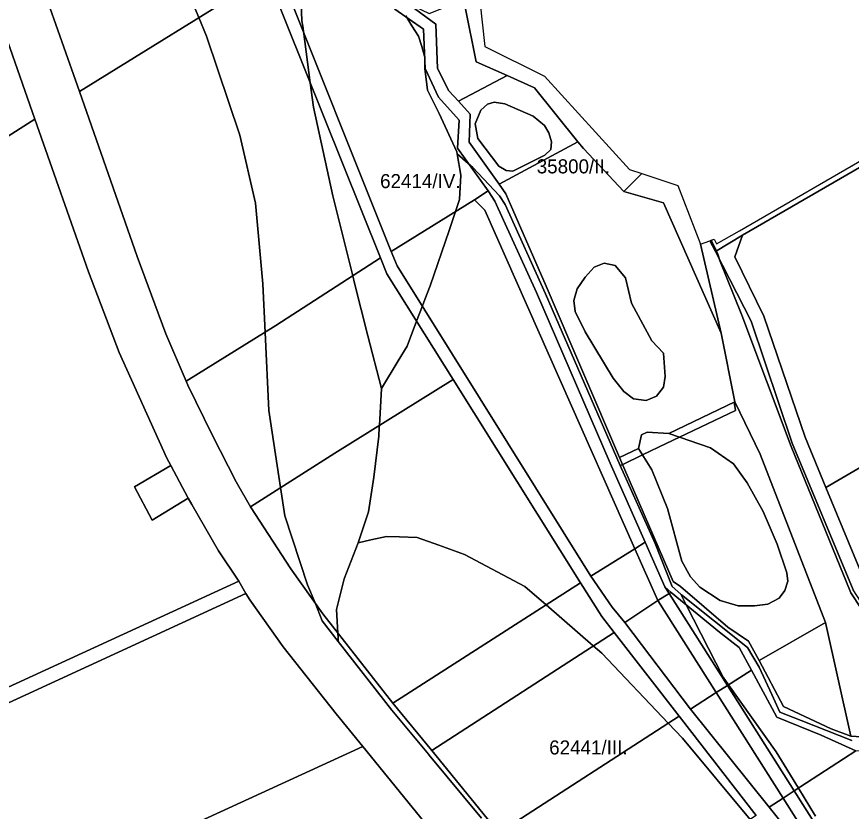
# Model space of a CAD drawing. Extents: x -522079 to -518833, y -1142400 to -1139961.
# Drawn here: x -520985.3 to -520688.5, y -1140520.9 to -1140238.4 of the extents above; entities that cross this region are included whole.
import ezdxf

# ---------------------------------------------------------------- set-up
doc = ezdxf.new("R2010")
doc.units = 0
for name, color, linetype in [('95560013', 7, 'Continuous'), ('95610013', 7, 'Continuous'), ('95620013', 7, 'Continuous'), ('95630013', 7, 'Continuous'), ('95640013', 7, 'Continuous'), ('95660013', 7, 'Continuous')]:
    doc.layers.add(name, color=color, linetype=linetype)

msp = doc.modelspace()

# ---------------------------------------------------------------- linework, layer by layer
at = {"layer": '95560013'}
for points in [[(-520697.54, -1140405.82), (-520704.93, -1140387.92), (-520719.64, -1140344.89), (-520729.96, -1140323.84), (-520727.12, -1140316.09), (-520610.57, -1140248.68), (-520489.41, -1140176.97), (-520443.64, -1140149.48), (-520437.53, -1140151.12), (-520407.86, -1140236.34), (-520563.45, -1140327.62)], [(-520896.25, -1140223.69), (-520963.03, -1140264.99), (-520975.5, -1140229.32), (-520909.48, -1140190.7)], [(-520863.77, -1140204.01), (-520859.87, -1140225.61), (-520850.88, -1140235.71), (-520840.6, -1140242.88), (-520840.04, -1140256.81), (-520835.3, -1140267.04), (-520827.93, -1140275.18), (-520828.6, -1140285.19), (-520817.67, -1140300.36), (-520822.46, -1140303.46), (-520852.13, -1140321.93), (-520892.27, -1140221.28)], [(-520963.03, -1140264.99), (-520896.25, -1140223.69), (-520855.89, -1140324.19), (-520893.13, -1140348.26), (-520925.04, -1140368.05), (-520932.27, -1140351.12), (-520942.5, -1140323.7)], [(-520407.86, -1140236.34), (-520389.24, -1140289.48), (-520535.21, -1140374.77), (-520673.87, -1140455.8), (-520683.48, -1140439.85), (-520697.54, -1140405.82), (-520563.45, -1140327.62)], [(-521144.75, -1140380.49), (-521166.55, -1140356.84), (-521138.04, -1140336), (-521105.44, -1140313.39), (-521071.25, -1140292.13), (-521029.36, -1140265.01), (-520991.34, -1140239.5), (-520978.89, -1140274.79)], [(-520943.46, -1140405.56), (-520937.19, -1140417.44), (-520924.28, -1140409.64), (-520923.06, -1140411.9), (-520913.58, -1140428.33), (-520906.37, -1140439.12), (-521031.07, -1140496.4), (-521039.03, -1140495.22), (-521144.75, -1140380.49), (-520978.89, -1140274.79), (-520959.74, -1140329.07), (-520948.85, -1140357.77), (-520931.92, -1140395.43), (-520930.52, -1140398.04)], [(-520853.68, -1140329.78), (-520830.07, -1140367.42), (-520872.15, -1140393.54), (-520902.19, -1140412.67), (-520907.24, -1140403.74), (-520915.77, -1140387.04), (-520924.44, -1140369.44), (-520925.04, -1140368.05), (-520893.13, -1140348.26), (-520855.89, -1140324.19)], [(-520781.06, -1140437.3), (-520765.49, -1140427.57), (-520757.32, -1140446.02), (-520769.04, -1140453.82), (-520773.55, -1140448.4)], [(-520851.49, -1140482.48), (-520784.75, -1140439.67), (-520777.25, -1140451.62), (-520772.84, -1140457.31), (-520837.71, -1140499.35)], [(-521174.07, -1140567.72), (-521038.29, -1140505.39), (-520903.84, -1140443.54), (-520902.4, -1140445.74), (-520890.58, -1140462.46), (-520871.65, -1140486.28), (-520862.22, -1140497.87), (-521134.28, -1140622.71), (-521175.11, -1140573.76)], [(-520757.32, -1140446.02), (-520736.54, -1140478.75), (-520745.68, -1140484.57), (-520769.04, -1140453.82)], [(-520837.71, -1140499.35), (-520772.84, -1140457.31), (-520749.72, -1140487.1), (-520813.81, -1140528.62)], [(-520736.54, -1140478.75), (-520712.75, -1140516.21), (-520717.71, -1140519.42), (-520745.68, -1140484.57)], [(-520785.9, -1140562.81), (-520813.81, -1140528.62), (-520749.72, -1140487.1), (-520722.28, -1140522.46), (-520735.82, -1140531.09)], [(-520862.22, -1140497.87), (-520765.71, -1140616.57), (-520897.82, -1140676.39), (-521036.95, -1140739.4), (-521134.28, -1140622.71)], [(-520712.75, -1140516.21), (-520692.27, -1140548.47), (-520693.7, -1140549.35), (-520717.71, -1140519.42)]]:
    msp.add_lwpolyline(points, close=True, dxfattribs=at)
msp.add_lwpolyline([(-520722.28, -1140522.46), (-520749.72, -1140487.1), (-520772.84, -1140457.31), (-520777.25, -1140451.62), (-520784.75, -1140439.67), (-520830.07, -1140367.42), (-520853.68, -1140329.78), (-520855.89, -1140324.19), (-520896.25, -1140223.69), (-520909.48, -1140190.7), (-520905.41, -1140188.32), (-520892.27, -1140221.28), (-520852.13, -1140321.93), (-520849.95, -1140326.96), (-520781.06, -1140437.3), (-520773.55, -1140448.4), (-520769.04, -1140453.82), (-520745.68, -1140484.57), (-520717.71, -1140519.42), (-520693.7, -1140549.35)], dxfattribs=at)
at = {"layer": '95610013'}
for points in [[(-520831.58, -1140264.76), (-520835.7, -1140256.78), (-520836.21, -1140241.05), (-520847.4, -1140232.82), (-520856.59, -1140222.67), (-520843.85, -1140234.81), (-520838.62, -1140237.3), (-520834.17, -1140235.54), (-520832.49, -1140233.14), (-520829.57, -1140196.57), (-520831.74, -1140193.15), (-520834.84, -1140193.48), (-520857.8, -1140202.58), (-520859.91, -1140204.51), (-520858.48, -1140201.26), (-520811.93, -1140174.77), (-520818.11, -1140203.91), (-520825.87, -1140235.03), (-520821.91, -1140254.48), (-520810.93, -1140259.32), (-520828.22, -1140268.46)], [(-520828.22, -1140268.46), (-520810.93, -1140259.32), (-520801.15, -1140263.64), (-520785.74, -1140282.9), (-520813.67, -1140297.99), (-520824.45, -1140283.03), (-520824.03, -1140273.06)], [(-520817.84, -1140269.53), (-520820.3, -1140271.64), (-520822.29, -1140276.46), (-520821.31, -1140281.75), (-520813.83, -1140291.57), (-520811.29, -1140293.11), (-520808.84, -1140293.29), (-520797.46, -1140287.61), (-520795.38, -1140285.61), (-520795.15, -1140282.87), (-520796.05, -1140279.66), (-520797.56, -1140277.1), (-520801.58, -1140273.72), (-520811.67, -1140269.37), (-520815.5, -1140268.8)], [(-520783.73, -1140285.25), (-520769.34, -1140300.61), (-520755.22, -1140304.57), (-520734.8, -1140350.95), (-520729.88, -1140375.38), (-520753.32, -1140386.65), (-520761.05, -1140386.08), (-520763.05, -1140387.08), (-520764.21, -1140391.88), (-520770.87, -1140395.08), (-520797.01, -1140334.21), (-520811.33, -1140301.33), (-520813.67, -1140297.99), (-520785.74, -1140282.9)], [(-520754.64, -1140366.29), (-520755.29, -1140358.03), (-520759.43, -1140353.7), (-520766.65, -1140340.21), (-520768.74, -1140331.28), (-520772.48, -1140326.88), (-520776.36, -1140326.07), (-520779.88, -1140327.47), (-520783.19, -1140331.06), (-520785.95, -1140335.16), (-520787.17, -1140339.26), (-520786.73, -1140343.23), (-520783.16, -1140350.46), (-520773.17, -1140366.91), (-520769.43, -1140371.66), (-520765.93, -1140374.29), (-520761.4, -1140374.89), (-520757.78, -1140373.33), (-520755.28, -1140370.09)], [(-520752.54, -1140443.09), (-520753.24, -1140443.52), (-520754.76, -1140441.12)], [(-520735.34, -1140457.3), (-520728.4, -1140462.65), (-520724, -1140470.78), (-520732.54, -1140476.21), (-520753.24, -1140443.52), (-520752.54, -1140443.09)], [(-520732.54, -1140476.21), (-520724, -1140470.78), (-520714.97, -1140487.48), (-520699.14, -1140493.81), (-520686.89, -1140499.45), (-520708.82, -1140513.67)], [(-520686.89, -1140499.45), (-520675.92, -1140498.77), (-520661.91, -1140491.42), (-520635.69, -1140488.94), (-520617.72, -1140496.63), (-520614.24, -1140500.69), (-520688.32, -1140546.05), (-520708.82, -1140513.67)]]:
    msp.add_lwpolyline(points, close=True, dxfattribs=at)
at = {"layer": '95620013'}
for points in [[(-520849.95, -1140326.96), (-520852.13, -1140321.93), (-520822.46, -1140303.46), (-520818.84, -1140307.19), (-520765.49, -1140427.57), (-520781.06, -1140437.3)], [(-520902.19, -1140412.67), (-520872.15, -1140393.54), (-520830.07, -1140367.42), (-520784.75, -1140439.67), (-520851.49, -1140482.48), (-520876.46, -1140450.75), (-520887.82, -1140434.78)]]:
    msp.add_lwpolyline(points, close=True, dxfattribs=at)
at = {"layer": '95630013'}
for points in [[(-520821.47, -1140225.09), (-520818.83, -1140248.97), (-520797.63, -1140259.52), (-520767.33, -1140292.73), (-520763.01, -1140294.16), (-520769.34, -1140300.61), (-520783.73, -1140285.25), (-520785.74, -1140282.9), (-520801.15, -1140263.64), (-520810.93, -1140259.32), (-520821.91, -1140254.48), (-520825.87, -1140235.03)], [(-520847.4, -1140232.82), (-520836.21, -1140241.05), (-520835.7, -1140256.78), (-520831.58, -1140264.76), (-520828.22, -1140268.46), (-520824.03, -1140273.06), (-520824.45, -1140283.03), (-520813.67, -1140297.99), (-520811.33, -1140301.33), (-520797.01, -1140334.21), (-520770.87, -1140395.08), (-520751.81, -1140439.25), (-520749.19, -1140441.04), (-520732.44, -1140455.44), (-520725.07, -1140460.42), (-520721.21, -1140467.33), (-520712.6, -1140483.62), (-520695.64, -1140491.57), (-520688.63, -1140494.17), (-520677.55, -1140494.96)], [(-520686.89, -1140499.45), (-520699.14, -1140493.81), (-520714.97, -1140487.48), (-520724, -1140470.78), (-520728.4, -1140462.65), (-520735.34, -1140457.3), (-520752.54, -1140443.09), (-520754.76, -1140441.12), (-520761.78, -1140425.25), (-520774.21, -1140397.13), (-520800.48, -1140336.51), (-520815.23, -1140303.96), (-520817.67, -1140300.36), (-520828.6, -1140285.19), (-520827.93, -1140275.18), (-520835.3, -1140267.04), (-520840.04, -1140256.81), (-520840.6, -1140242.88), (-520850.88, -1140235.71)], [(-520677.55, -1140494.96), (-520688.63, -1140494.17), (-520697.67, -1140453.81), (-520720.9, -1140393.9), (-520729.88, -1140375.38), (-520734.8, -1140350.95), (-520755.22, -1140304.57), (-520769.34, -1140300.61), (-520763.01, -1140294.16), (-520750.13, -1140298.42), (-520742.16, -1140319.24), (-520738.8, -1140318.04), (-520736.79, -1140321.94), (-520724.04, -1140346.68), (-520709.46, -1140390.03), (-520687.78, -1140442.24)]]:
    msp.add_lwpolyline(points, dxfattribs=at)
for points in [[(-520795.15, -1140282.87), (-520795.38, -1140285.61), (-520797.46, -1140287.61), (-520808.84, -1140293.29), (-520811.29, -1140293.11), (-520813.83, -1140291.57), (-520821.31, -1140281.75), (-520822.29, -1140276.46), (-520820.3, -1140271.64), (-520817.84, -1140269.53), (-520815.5, -1140268.8), (-520811.67, -1140269.37), (-520801.58, -1140273.72), (-520797.56, -1140277.1), (-520796.05, -1140279.66)], [(-520768.74, -1140331.28), (-520766.65, -1140340.21), (-520759.43, -1140353.7), (-520755.29, -1140358.03), (-520754.64, -1140366.29), (-520755.28, -1140370.09), (-520757.78, -1140373.33), (-520761.4, -1140374.89), (-520765.93, -1140374.29), (-520769.43, -1140371.66), (-520773.17, -1140366.91), (-520783.16, -1140350.46), (-520786.73, -1140343.23), (-520787.17, -1140339.26), (-520785.95, -1140335.16), (-520783.19, -1140331.06), (-520779.88, -1140327.47), (-520776.36, -1140326.07), (-520772.48, -1140326.88)], [(-520729.88, -1140375.38), (-520720.9, -1140393.9), (-520697.67, -1140453.81), (-520721.21, -1140467.33), (-520725.07, -1140460.42), (-520732.44, -1140455.44), (-520749.19, -1140441.04), (-520751.81, -1140439.25), (-520770.87, -1140395.08), (-520764.21, -1140391.88), (-520759.4, -1140399.48), (-520753.83, -1140413.22), (-520748.72, -1140432.03), (-520745.71, -1140437.58), (-520742.3, -1140441.21), (-520735.07, -1140445.99), (-520728.76, -1140447.85), (-520722.88, -1140447.92), (-520718.16, -1140447.28), (-520714.17, -1140445.14), (-520712.14, -1140442.41), (-520711.04, -1140439.09), (-520711.41, -1140436.09), (-520714.9, -1140426), (-520719.87, -1140414.3), (-520725.51, -1140404.14), (-520730.43, -1140397.36), (-520738.54, -1140391.69), (-520753.32, -1140386.65)], [(-520753.32, -1140386.65), (-520738.54, -1140391.69), (-520730.43, -1140397.36), (-520725.51, -1140404.14), (-520719.87, -1140414.3), (-520714.9, -1140426), (-520711.41, -1140436.09), (-520711.04, -1140439.09), (-520712.14, -1140442.41), (-520714.17, -1140445.14), (-520718.16, -1140447.28), (-520722.88, -1140447.92), (-520728.76, -1140447.85), (-520735.07, -1140445.99), (-520742.3, -1140441.21), (-520745.71, -1140437.58), (-520748.72, -1140432.03), (-520753.83, -1140413.22), (-520759.4, -1140399.48), (-520764.21, -1140391.88), (-520763.05, -1140387.08), (-520761.05, -1140386.08)]]:
    msp.add_lwpolyline(points, close=True, dxfattribs=at)
at = {"layer": '95640013'}
for points in [[(-520489.41, -1140176.97), (-520610.57, -1140248.68), (-520727.12, -1140316.09), (-520736.79, -1140321.94), (-520738.8, -1140318.04), (-520737.2, -1140317.47), (-520736.37, -1140319.22), (-520728.21, -1140314.51), (-520611.62, -1140247.2), (-520491.09, -1140175.17)], [(-520989.57, -1140189.1), (-520981.4, -1140212.45), (-520975.5, -1140229.32), (-520963.03, -1140264.99), (-520942.5, -1140323.7), (-520932.27, -1140351.12), (-520925.04, -1140368.05), (-520924.44, -1140369.44), (-520915.77, -1140387.04), (-520907.24, -1140403.74), (-520902.19, -1140412.67), (-520887.82, -1140434.78), (-520876.46, -1140450.75), (-520851.49, -1140482.48), (-520837.71, -1140499.35), (-520813.81, -1140528.62)], [(-520765.71, -1140616.57), (-520862.22, -1140497.87), (-520871.65, -1140486.28), (-520890.58, -1140462.46), (-520902.4, -1140445.74), (-520903.84, -1140443.54), (-520906.37, -1140439.12), (-520913.58, -1140428.33), (-520923.06, -1140411.9), (-520924.28, -1140409.64), (-520930.52, -1140398.04), (-520931.92, -1140395.43), (-520948.85, -1140357.77), (-520959.74, -1140329.07), (-520978.89, -1140274.79), (-520991.34, -1140239.5)], [(-520560.63, -1140549.81), (-520611.7, -1140490.5), (-520625.05, -1140483.49), (-520666, -1140475.86), (-520687.78, -1140442.24), (-520709.46, -1140390.03), (-520724.04, -1140346.68), (-520736.79, -1140321.94), (-520727.12, -1140316.09), (-520729.96, -1140323.84), (-520719.64, -1140344.89), (-520704.93, -1140387.92), (-520697.54, -1140405.82), (-520683.48, -1140439.85), (-520673.87, -1140455.8), (-520666.98, -1140467.24), (-520659.41, -1140472.47), (-520623.97, -1140478.75), (-520608.7, -1140486.32), (-520592.52, -1140504.62), (-520587.65, -1140510.13), (-520562.49, -1140540.48)]]:
    msp.add_lwpolyline(points, dxfattribs=at)
for points in [[(-520822.46, -1140303.46), (-520817.67, -1140300.36), (-520815.23, -1140303.96), (-520800.48, -1140336.51), (-520774.21, -1140397.13), (-520761.78, -1140425.25), (-520765.49, -1140427.57), (-520818.84, -1140307.19)], [(-520943.46, -1140405.56), (-520930.52, -1140398.04), (-520924.28, -1140409.64), (-520937.19, -1140417.44)], [(-520754.76, -1140441.12), (-520753.24, -1140443.52), (-520757.32, -1140446.02), (-520765.49, -1140427.57), (-520761.78, -1140425.25)], [(-521428.47, -1140683.93), (-521438.02, -1140688.47), (-521441.99, -1140684.63), (-521355.48, -1140644.9), (-521309.07, -1140623.96), (-521152, -1140551.52), (-521060.49, -1140509.3), (-521045.09, -1140502.65), (-521031.07, -1140496.4), (-520906.37, -1140439.12), (-520903.84, -1140443.54), (-521038.29, -1140505.39), (-521174.07, -1140567.72), (-521187.8, -1140573.75), (-521306.81, -1140628.37)], [(-520757.32, -1140446.02), (-520753.24, -1140443.52), (-520732.54, -1140476.21), (-520736.54, -1140478.75)], [(-520721.21, -1140467.33), (-520697.67, -1140453.81), (-520688.63, -1140494.17), (-520695.64, -1140491.57), (-520712.6, -1140483.62)], [(-520732.54, -1140476.21), (-520708.82, -1140513.67), (-520712.75, -1140516.21), (-520736.54, -1140478.75)], [(-520708.82, -1140513.67), (-520688.32, -1140546.05), (-520692.27, -1140548.47), (-520712.75, -1140516.21)]]:
    msp.add_lwpolyline(points, close=True, dxfattribs=at)
at = {"layer": '95660013'}
for points in [[(-520884.7, -1140216.69), (-520883.86, -1140239.89), (-520883.61, -1140241.74), (-520883.37, -1140243.6), (-520880.92, -1140261.86), (-520879.76, -1140270.51), (-520872.93, -1140302.05), (-520865.81, -1140330.6), (-520865.18, -1140333.13), (-520860.4, -1140351.86), (-520855.62, -1140370.6), (-520856.32, -1140383.71), (-520856.36, -1140384.4), (-520856.53, -1140387.51), (-520858.35, -1140402.14), (-520860.17, -1140414.48), (-520863.82, -1140425.45), (-520868.83, -1140438.25), (-520871.56, -1140449.22), (-520871.11, -1140457.55), (-520871.02, -1140459.15), (-520870.94, -1140460.53), (-520876.68, -1140453.17), (-520879.22, -1140446.87), (-520881.84, -1140440.36), (-520889.98, -1140415.87), (-520891.48, -1140405.85), (-520895.59, -1140378.43), (-520896.97, -1140350.64), (-520897.83, -1140333.39), (-520900.36, -1140304.68), (-520905.97, -1140280.47), (-520917.76, -1140245.28), (-520920.51, -1140238.69), (-520931.79, -1140211.78)], [(-520931.79, -1140211.78), (-520920.51, -1140238.69), (-520917.76, -1140245.28), (-520905.97, -1140280.47), (-520900.36, -1140304.68), (-520897.83, -1140333.39), (-520896.97, -1140350.64), (-520895.59, -1140378.43), (-520891.48, -1140405.85), (-520889.98, -1140415.87), (-520881.84, -1140440.36), (-520879.22, -1140446.87), (-520876.68, -1140453.17), (-520870.94, -1140460.53), (-520851.87, -1140485.02), (-520838.89, -1140500.65), (-520838.57, -1140501.03), (-520819.98, -1140523.33)], [(-520846.96, -1140238.06), (-520846.54, -1140238.74), (-520844.73, -1140241.63), (-520842.4, -1140245.37), (-520841.27, -1140249.01), (-520840.22, -1140252.39), (-520840.17, -1140252.54), (-520840.12, -1140252.69), (-520840.12, -1140254.69), (-520840.12, -1140256.8), (-520839.21, -1140264.57), (-520835.11, -1140272.8), (-520828.73, -1140286.51), (-520828.62, -1140287.17), (-520827.37, -1140294.74), (-520827.82, -1140303.42), (-520829.24, -1140307.68), (-520831.47, -1140314.39), (-520838.3, -1140334.04), (-520840.19, -1140338.98), (-520841.04, -1140341.23), (-520843.11, -1140346.63), (-520846.5, -1140355.52), (-520849.66, -1140360.74), (-520855.62, -1140370.6), (-520860.4, -1140351.86), (-520865.18, -1140333.13), (-520865.81, -1140330.6), (-520872.93, -1140302.05), (-520879.76, -1140270.51), (-520880.92, -1140261.86), (-520883.37, -1140243.6), (-520883.61, -1140241.74), (-520883.86, -1140239.89), (-520884.7, -1140216.69)], [(-520821.47, -1140225.09), (-520818.83, -1140248.97), (-520797.63, -1140259.52), (-520767.33, -1140292.73), (-520763.01, -1140294.16), (-520750.13, -1140298.42), (-520742.16, -1140319.24), (-520734.8, -1140350.95), (-520729.88, -1140375.38), (-520730.16, -1140375.51), (-520729.61, -1140378.41), (-520749.55, -1140387.93), (-520754.34, -1140390.21), (-520762.73, -1140394.22), (-520769.79, -1140397.59), (-520770.64, -1140398), (-520797.28, -1140336.9), (-520811.58, -1140305.16), (-520813.62, -1140302.12), (-520823.03, -1140292.05), (-520824.71, -1140290.58), (-520828.62, -1140287.17), (-520828.73, -1140286.51), (-520835.11, -1140272.8), (-520839.21, -1140264.57), (-520840.12, -1140256.8), (-520840.12, -1140254.69), (-520840.12, -1140252.69), (-520840.17, -1140252.54), (-520840.22, -1140252.39), (-520841.27, -1140249.01), (-520842.4, -1140245.37), (-520844.73, -1140241.63), (-520846.54, -1140238.74), (-520846.96, -1140238.06)], [(-520666.58, -1140476.66), (-520688.6, -1140443.21), (-520688.85, -1140442.65), (-520709.83, -1140391.18), (-520727.37, -1140344.51), (-520735.41, -1140324.82), (-520735.53, -1140324.37), (-520735.77, -1140323.51), (-520735.96, -1140322.84), (-520736.47, -1140321.75), (-520738.3, -1140317.86), (-520737.2, -1140317.47), (-520736.37, -1140319.22), (-520728.21, -1140314.51), (-520679.51, -1140286.39)], [(-520724.41, -1140523.82), (-520748.55, -1140494.92), (-520753.6, -1140489.61), (-520777.25, -1140464.76), (-520780.27, -1140462.13), (-520797.04, -1140447.55), (-520804.59, -1140440.99), (-520826, -1140429.57), (-520835.24, -1140426.31), (-520842.86, -1140423.62), (-520849.16, -1140423.36), (-520853.79, -1140423.17), (-520859.39, -1140424.44), (-520863.82, -1140425.45), (-520860.17, -1140414.48), (-520858.35, -1140402.14), (-520856.53, -1140387.51), (-520856.36, -1140384.4), (-520856.32, -1140383.71), (-520855.62, -1140370.6), (-520849.66, -1140360.74), (-520846.5, -1140355.52), (-520843.11, -1140346.63), (-520841.04, -1140341.23), (-520840.19, -1140338.98), (-520838.3, -1140334.04), (-520831.47, -1140314.39), (-520829.24, -1140307.68), (-520827.82, -1140303.42), (-520827.37, -1140294.74), (-520828.62, -1140287.17), (-520824.71, -1140290.58), (-520823.03, -1140292.05), (-520813.62, -1140302.12), (-520811.58, -1140305.16), (-520797.28, -1140336.9), (-520770.64, -1140398), (-520758.19, -1140425.7), (-520752.15, -1140441.01), (-520749.16, -1140443.69), (-520747.22, -1140447.48), (-520734.04, -1140473.22), (-520732.11, -1140475.94), (-520715.23, -1140499.75), (-520707.3, -1140512.68), (-520701.19, -1140522.65)], [(-520688.28, -1140495.8), (-520706.32, -1140488.67), (-520713.93, -1140485.66), (-520716.78, -1140479.4), (-520721.2, -1140469.67), (-520725.4, -1140462.65), (-520748.84, -1140443.98), (-520749.16, -1140443.69), (-520752.15, -1140441.01), (-520758.19, -1140425.7), (-520770.64, -1140398), (-520769.79, -1140397.59), (-520762.73, -1140394.22), (-520754.34, -1140390.21), (-520749.55, -1140387.93), (-520729.61, -1140378.41), (-520730.16, -1140375.51), (-520729.88, -1140375.38), (-520734.8, -1140350.95), (-520742.16, -1140319.24), (-520738.8, -1140318.04), (-520738.3, -1140317.86), (-520736.47, -1140321.75), (-520735.96, -1140322.84), (-520735.77, -1140323.51), (-520735.53, -1140324.37), (-520735.41, -1140324.82), (-520727.37, -1140344.51), (-520709.83, -1140391.18), (-520688.85, -1140442.65), (-520688.6, -1140443.21), (-520666.58, -1140476.66)], [(-520819.98, -1140523.33), (-520838.57, -1140501.03), (-520838.89, -1140500.65), (-520851.87, -1140485.02), (-520870.94, -1140460.53), (-520871.02, -1140459.15), (-520871.11, -1140457.55), (-520871.56, -1140449.22), (-520868.83, -1140438.25), (-520863.82, -1140425.45), (-520859.39, -1140424.44), (-520853.79, -1140423.17), (-520849.16, -1140423.36), (-520842.86, -1140423.62), (-520835.24, -1140426.31), (-520826, -1140429.57), (-520804.59, -1140440.99), (-520797.04, -1140447.55), (-520780.27, -1140462.13), (-520777.25, -1140464.76), (-520753.6, -1140489.61), (-520748.55, -1140494.92), (-520724.41, -1140523.82)], [(-520701.19, -1140522.65), (-520707.3, -1140512.68), (-520715.23, -1140499.75), (-520732.11, -1140475.94), (-520734.04, -1140473.22), (-520747.22, -1140447.48), (-520749.16, -1140443.69), (-520748.84, -1140443.98), (-520725.4, -1140462.65), (-520721.2, -1140469.67), (-520716.78, -1140479.4), (-520713.93, -1140485.66), (-520706.32, -1140488.67), (-520688.28, -1140495.8)]]:
    msp.add_lwpolyline(points, dxfattribs=at)

# ---------------------------------------------------------------- texts
for s, rotation, p in [('35800/II.', 360, (-520800.36, -1140294.11)), ('62414/IV.', 0, (-520856.07, -1140299.36)), ('62441/III.', 360, (-520795.93, -1140500.74))]:
    msp.add_text(s, height=5, rotation=rotation, dxfattribs=at).set_placement(p)

doc.saveas('drawing.dxf')
